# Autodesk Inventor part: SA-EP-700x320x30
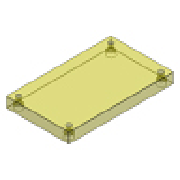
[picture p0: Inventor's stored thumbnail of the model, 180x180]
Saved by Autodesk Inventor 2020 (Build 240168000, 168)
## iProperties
Created: 2019-01
Part Number: SA-EP-700x320x30
Material: S 55 C
Description: Ejector Plate
Document SubType Name: Modeling
Designer: LENOVO-CADCIM
Standard Revision: 1
Manufacturer: FUTABA
Language: en-US
Size Designation: 700x320x30
Categories: <MemberInstance><Categories><Category DisplayName="Mold" InternalName="349578f2-f4d4-4954-8c09-8e99297a61c0" Mnemonic="MOLD"><Category DisplayName="Mold Plates"
Density: 7.85 g/cm^3
Appearance: Clear - Yellow
IsCustomPart: 1
Author: LENOVO-CADCIM
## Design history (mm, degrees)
sketch "Sketch1"
  geometry: L1 (-160, 350)-(160, 350); L2 (160, 350)-(160, -350); L3 (160, -350)-(-160, -350); L4 (-160, -350)-(-160, 350); 4 further points
  constraints: 8 end point, 2 midpoint, 2 parallel, 1 horizontal, 1 horizontal alignment, 1 perpendicular, 1 vertical alignment
  dimensions: "d74" = 147 horizontal distance of point (0, 0) point (-147, 337) (= 0.5 x S2_W); "d75" = 337 vertical distance of point (0, 0) point (-147, 337) (= 0.5 x S2_L); "d92" = 320 distance between parallel lines of L2 L4 (= W_); "d93" = 700 distance between parallel lines of L3 L1 (= L)
extrude "Extrusion1" new body sketch "Sketch1" distance "d20" = 30 (= H_); taper "d30" = 0 deg
body "Solid1"
hole "Hole1" sketch "Sketch1" diameter "d76" = 14 (= S2_d1); stored, may be unused: countersink angle "d80" = 90 deg, drill point angle "d82" = 0 deg; dims "d77" = 6, "d78" = 20 (= S2_d2), "d79" = 13 (= S2_k), "d81" = 30 (= H_)
pattern_linear "Rectangular Pattern1" dims "d85" = 674 (computed from S2_L, Nl), "d88" = 294 (computed from S2_W, Nw)
chamfer "Chamfer1" distance "d89" = 0.5; stored, may be unused: second distance "d90" = 2, angle "d91" = 45 deg
other parameters: "L" = 700 [user parameter; used in 1 equation term], "W_" = 320 [user parameter; used in 1 equation term], "H_" = 30 [user parameter; used in 2 equation terms], "S2_W" = 294 [user parameter; used in 2 equation terms], "S2_d1" = 14 [user parameter; used in 1 equation term], "S2_d2" = 20 [user parameter; used in 1 equation term], "S2_k" = 13 [user parameter; used in 1 equation term], "S2_L" = 674 [user parameter; used in 2 equation terms]
